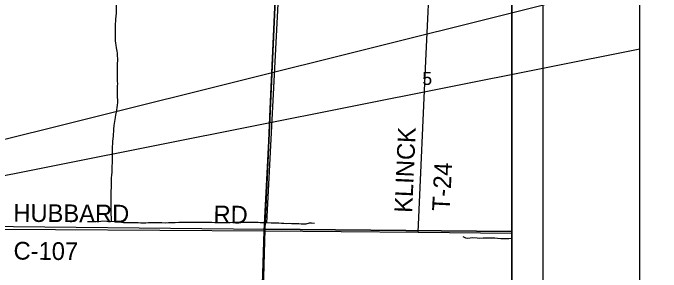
# Model space of a CAD drawing. Extents: x 0 to 34, y 0 to 22.
# Drawn here: x 7.301 to 9.379, y 17.366 to 18.196 of the extents above; entities that cross this region are included whole.
import ezdxf

# ---------------------------------------------------------------- set-up
doc = ezdxf.new("R2010")
doc.units = 0
for name, color, linetype in [('Default', 7, 'Continuous'), ('GM_X_County_Road', 7, 'Continuous'), ('GM_X_County_Road_Text', 7, 'Continuous'), ('GM_X_Minor_River', 7, 'Continuous'), ('GM_X_Section', 7, 'Continuous'), ('GM_X_Section_Text', 7, 'Continuous'), ('GM_X_Township_Road', 7, 'Continuous'), ('GM_X_Township_Road_Text', 7, 'Continuous'), ('SH_Cut_Line', 7, 'Continuous'), ('SH_Data', 7, 'Continuous'), ('SH_Text', 7, 'Continuous')]:
    doc.layers.add(name, color=color, linetype=linetype)

msp = doc.modelspace()

# ---------------------------------------------------------------- linework, layer by layer
at = {"layer": 'Default'}
msp.add_lwpolyline([(8.9, 16.9874), (8.9, 20.9)], dxfattribs=at)
for points in [[(8.9, 17.4952), (8.9, 18.4963), (8.1531, 18.4998), (8.1087, 17.5031)], [(8.9, 16.4924), (8.9, 17.4952), (8.1087, 17.5031), (8.0805, 16.4987)]]:
    msp.add_lwpolyline(points, close=True, dxfattribs=at)
at = {"layer": 'GM_X_County_Road'}
msp.add_line((8.5995, 17.493), (8.9, 17.4898), dxfattribs=at)
msp.add_lwpolyline([(7.1023, 17.5041), (8.1067, 17.4977), (8.5995, 17.493)], dxfattribs=at)
at = {"layer": 'GM_X_Minor_River'}
msp.add_line((8.1576, 18.3777), (8.1136, 17.5233), dxfattribs=at)
for points in [[(7.6313, 18.2233), (7.6314, 18.1944), (7.6307, 18.1849), (7.6296, 18.1762), (7.6292, 18.1697), (7.6285, 18.161), (7.6286, 18.1515), (7.6282, 18.1409), (7.6286, 18.1314), (7.6283, 18.1238), (7.6287, 18.117), (7.6291, 18.1059), (7.6299, 18.0984), (7.6307, 18.0919), (7.6322, 18.0839), (7.6342, 18.0733), (7.635, 18.0665), (7.6354, 18.0566), (7.6358, 18.0502), (7.6358, 18.0422), (7.6355, 18.0342), (7.6355, 18.0263), (7.6352, 18.013), (7.6352, 18.0004), (7.6349, 17.9898), (7.6349, 17.9834), (7.6353, 17.9769), (7.6357, 17.9682), (7.6354, 17.9617), (7.6354, 17.953), (7.6347, 17.9446), (7.6351, 17.9367), (7.6355, 17.9245), (7.6359, 17.9169), (7.6359, 17.9082), (7.6352, 17.8998), (7.6341, 17.8922), (7.6326, 17.8846), (7.6315, 17.8778), (7.63, 17.8691), (7.6281, 17.8603), (7.627, 17.8539), (7.6252, 17.8417), (7.6245, 17.8345), (7.6234, 17.8235), (7.623, 17.8151), (7.6223, 17.8087), (7.6219, 17.8011), (7.6212, 17.7935), (7.6201, 17.784), (7.6197, 17.7764), (7.6194, 17.7673), (7.6191, 17.7585), (7.6187, 17.7517), (7.6188, 17.7339), (7.6188, 17.7244), (7.6185, 17.7149), (7.6181, 17.7043), (7.6182, 17.6925), (7.6174, 17.6841), (7.6167, 17.6765), (7.6156, 17.6667), (7.6153, 17.6602), (7.6153, 17.6397), (7.6146, 17.6215), (7.6147, 17.6036), (7.6144, 17.5957), (7.6145, 17.5558), (7.6149, 17.549), (7.6157, 17.541), (7.6161, 17.5338), (7.6158, 17.5273)], [(7.6158, 17.5273), (7.6112, 17.5262), (7.6021, 17.5273), (7.5892, 17.528), (7.5824, 17.5279), (7.568, 17.5263), (7.5607, 17.5259), (7.5467, 17.5258), (7.5395, 17.5262)], [(8.2673, 17.5209), (8.2582, 17.5216), (8.251, 17.5223), (8.2396, 17.5192), (8.2328, 17.5184), (8.2248, 17.5188), (8.2172, 17.5195), (8.2047, 17.5202), (8.1941, 17.5201), (8.1861, 17.5205), (8.1789, 17.5204), (8.1698, 17.5215), (8.1614, 17.5215), (8.1531, 17.5222), (8.1444, 17.5222), (8.1349, 17.5221), (8.1284, 17.5225), (8.1094, 17.5231), (8.1003, 17.5234), (8.0935, 17.5234), (8.0871, 17.5238), (8.0791, 17.5241), (8.0692, 17.524), (8.0567, 17.5244), (8.0487, 17.5247), (8.0411, 17.5246), (8.029, 17.5242), (8.0225, 17.5242), (8.0146, 17.5237), (8.0051, 17.5237), (7.9971, 17.5233), (7.9785, 17.5232), (7.9664, 17.5227), (7.9599, 17.5231), (7.9486, 17.523), (7.9387, 17.5237), (7.9292, 17.5237), (7.9182, 17.5244), (7.8977, 17.5243), (7.8894, 17.5246), (7.8749, 17.5245), (7.8647, 17.5241), (7.8518, 17.5244), (7.8419, 17.5244), (7.8328, 17.5239), (7.8211, 17.5235), (7.8085, 17.5227), (7.7998, 17.5226), (7.7892, 17.5222), (7.7782, 17.5229), (7.7649, 17.5232), (7.7581, 17.5232), (7.7463, 17.5235), (7.7353, 17.5227), (7.7273, 17.5222), (7.7186, 17.5218), (7.7106, 17.5221), (7.7023, 17.5229), (7.6932, 17.5236), (7.6852, 17.5235), (7.6773, 17.5231), (7.6628, 17.523), (7.6552, 17.5226), (7.6488, 17.5237), (7.6158, 17.5273)], [(8.7429, 17.4795), (8.7512, 17.4753), (8.7591, 17.474), (8.7663, 17.4747), (8.7751, 17.4758), (8.7891, 17.4756), (8.7982, 17.4744), (8.8088, 17.4747), (8.816, 17.4746), (8.8236, 17.4749), (8.8312, 17.4756), (8.8391, 17.4755), (8.8456, 17.4751), (8.8547, 17.4742), (8.8649, 17.4726), (8.8717, 17.4725), (8.8804, 17.4728), (8.8903, 17.4731), (8.9, 17.4737)]]:
    msp.add_lwpolyline(points, dxfattribs=at)
at = {"layer": 'GM_X_Section'}
msp.add_lwpolyline([(7.1, 17.5132), (8.1087, 17.5031), (8.0805, 16.4987), (7.0767, 16.5008), (7.0769, 16.5061), (7.0999, 17.5106)], close=True, dxfattribs=at)
at = {"layer": 'GM_X_Township_Road'}
for points in [[(8.1256, 17.8887), (8.1488, 18.3996), (8.1546, 18.9633)], [(8.5995, 17.493), (8.6243, 18.0427), (8.6409, 18.3804), (8.6486, 18.4894)], [(8.1067, 17.4977), (8.121, 17.7853), (8.1256, 17.8887)], [(8.0937, 16.9944), (8.1012, 17.3253), (8.1067, 17.4977)]]:
    msp.add_lwpolyline(points, dxfattribs=at)
at = {"layer": 'SH_Cut_Line'}
msp.add_lwpolyline([(8.9, 14.1), (8.9, 20.9)], dxfattribs=at)
at = {"layer": 'SH_Data'}
for p, q in [((9, 21), (9, 14)), ((8.9, 20.9), (8.9, 14.1))]:
    msp.add_line(p, q, dxfattribs=at)
at = {"layer": 'SH_Text'}
for points in [[(9.3111, 18.299), (4.9771, 17.2181), (9.3111, 18.0801)], [(9.3111, 18.299), (11.9158, 18.299), (11.9158, 16.6684), (9.3111, 16.6684)]]:
    msp.add_lwpolyline(points, close=True, dxfattribs=at)

# ---------------------------------------------------------------- texts
at = {"layer": 'GM_X_County_Road_Text'}
for s, rotation, p in [('HUBBARD', 359.5779, (7.302, 17.5266)), ('RD', 359.5045, (7.9437, 17.5216)), ('C-107', 359.4494, (7.3026, 17.4055))]:
    msp.add_text(s, height=0.05682, rotation=rotation, dxfattribs=at).set_placement(p)
at = {"layer": 'GM_X_Section_Text'}
msp.add_text('5', height=0.0419, rotation=0, dxfattribs=at).set_placement((8.6135, 17.9648))
at = {"layer": 'GM_X_Township_Road_Text'}
for s, rotation, p in [('KLINCK', 87.4552, (8.5804, 17.5544)), ('T-24', 87.1731, (8.7012, 17.5594))]:
    msp.add_text(s, height=0.05682, rotation=rotation, dxfattribs=at).set_placement(p)

doc.saveas('drawing.dxf')
